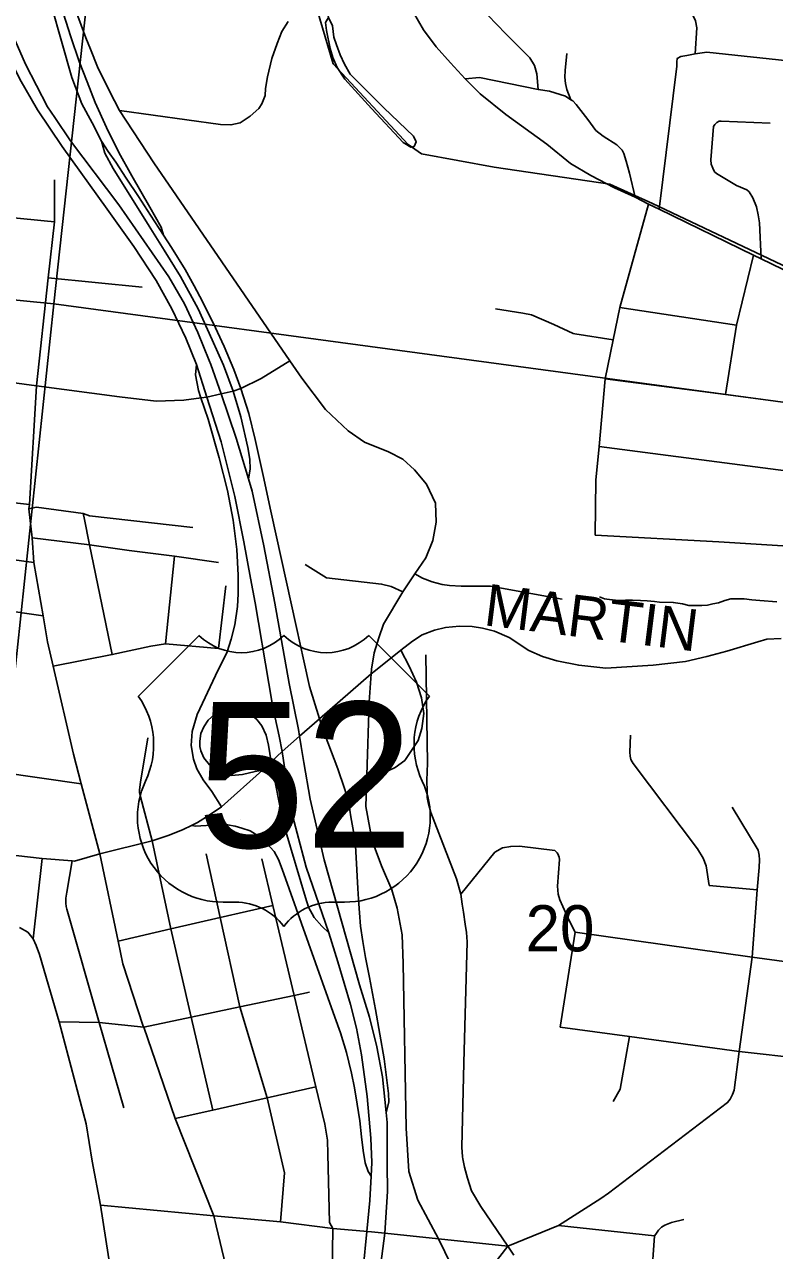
# Model space of a CAD drawing. Extents: x -8.2 to 38.5, y -0.1 to 21.9.
# Drawn here: x 5.706 to 6.385, y 16.265 to 17.376 of the extents above; entities that cross this region are included whole.
import ezdxf

# ---------------------------------------------------------------- set-up
doc = ezdxf.new("R2010")
doc.units = 0
for name, color, linetype in [('GM_X_Adjacent_County_Text', 7, 'Continuous'), ('GM_X_Airport_Location_Class_3', 7, 'Continuous'), ('GM_X_County_Road_Text', 7, 'Continuous'), ('GM_X_Interstate_Location', 7, 'Continuous'), ('GM_X_Major_Lake', 7, 'Continuous'), ('GM_X_Minor_River', 7, 'Continuous'), ('GM_X_State_Location', 7, 'Continuous'), ('GM_X_Township_Road_Text', 7, 'Continuous'), ('GM_X_Township_Subdivision', 7, 'Continuous'), ('GM_X_Township_Subdivision_Text', 7, 'Continuous'), ('GM_X_Township_Text', 7, 'Continuous'), ('GM_X_US_Location', 7, 'Continuous')]:
    doc.layers.add(name, color=color, linetype=linetype)

msp = doc.modelspace()

# ---------------------------------------------------------------- linework, layer by layer
at = {"layer": 'GM_X_Adjacent_County_Text'}
for points in [[(4.7544, 17.3899), (4.8395, 18.1926), (5.838, 18.0925), (5.7325, 17.1233), (5.0356, 17.1922)], [(5.0356, 17.1922), (5.7325, 17.1233), (5.6225, 16.0867), (4.6267, 16.1928), (4.6777, 16.67)]]:
    msp.add_lwpolyline(points, dxfattribs=at)
for points in [[(6.8589, 17.9964), (6.7536, 16.9855), (5.7325, 17.1233), (5.838, 18.0925)], [(5.7325, 17.1233), (6.7536, 16.9855), (6.65, 15.9814), (5.6225, 16.0867)]]:
    msp.add_lwpolyline(points, close=True, dxfattribs=at)
at = {"layer": 'GM_X_Airport_Location_Class_3'}
for p, q in [((5.9523, 16.83), (5.9292, 16.9355)), ((6.0469, 16.8096), (6.0238, 16.791)), ((6.016, 16.6962), (6.0182, 16.7627)), ((5.8844, 16.6676), (5.9215, 16.7008))]:
    msp.add_line(p, q, dxfattribs=at)
for points in [[(5.8671, 17.1255), (5.8595, 17.1397), (5.8513, 17.1545), (5.839, 17.1744), (5.8317, 17.1856), (5.82, 17.2036), (5.8091, 17.2205), (5.7981, 17.2373), (5.7887, 17.2517), (5.7817, 17.2613), (5.7756, 17.2708), (5.7672, 17.2875), (5.7579, 17.3046), (5.7488, 17.3285), (5.7393, 17.3613), (5.7305, 17.3922), (5.7205, 17.4265), (5.7107, 17.455)], [(5.6577, 17.4416), (5.6636, 17.4182), (5.675, 17.3847), (5.6851, 17.361), (5.7015, 17.3269), (5.7176, 17.2991), (5.74, 17.266), (5.7809, 17.2092), (5.8048, 17.1752), (5.8251, 17.1446), (5.8393, 17.1188), (5.8519, 17.0921), (5.8616, 17.0684)], [(5.7655, 17.3541), (5.7613, 17.3643), (5.75, 17.3956)], [(6.0487, 16.8623), (6.0597, 16.8786), (6.0695, 16.8931), (6.0759, 16.9089), (6.079, 16.9255), (6.0782, 16.9426), (6.07, 16.96), (6.0592, 16.973), (6.0486, 16.9825), (6.0356, 16.9891), (6.0139, 16.998), (5.9992, 17.0082), (5.9787, 17.0276), (5.9572, 17.0559), (5.9463, 17.0717), (5.8231, 17.2512), (5.792, 17.2985), (5.7828, 17.3162), (5.772, 17.3382), (5.7655, 17.3541)], [(5.9292, 16.9355), (5.9221, 16.9677), (5.9149, 17.0004), (5.909, 17.0238), (5.9018, 17.0467), (5.8954, 17.0637), (5.8867, 17.0848), (5.8768, 17.1061), (5.8685, 17.1228), (5.8671, 17.1255)], [(5.8616, 17.0684), (5.8609, 17.0589), (5.8634, 17.0449), (5.8657, 17.0381), (5.8723, 17.0188), (5.8821, 16.9838), (5.8897, 16.9541), (5.895, 16.9274), (5.8983, 16.9006), (5.8995, 16.8774)], [(5.8995, 16.8774), (5.8996, 16.8764), (5.8996, 16.8605), (5.8988, 16.849), (5.8965, 16.8324), (5.893, 16.8193), (5.8895, 16.8079), (5.879, 16.7864), (5.8622, 16.7511), (5.8579, 16.7359), (5.8569, 16.723), (5.8589, 16.7107), (5.862, 16.702), (5.8676, 16.6921), (5.8755, 16.6814), (5.8844, 16.6676)], [(6.0182, 16.7627), (6.0202, 16.7923), (6.0226, 16.8072), (6.027, 16.8206), (6.0312, 16.8329), (6.0487, 16.8623)], [(5.9733, 16.7473), (5.9642, 16.7765), (5.9589, 16.7997), (5.9523, 16.83)], [(6.016, 16.6962), (6.0239, 16.6965), (6.0308, 16.6981), (6.0416, 16.703), (6.0505, 16.7096), (6.0564, 16.7185), (6.0627, 16.7277), (6.0659, 16.7386), (6.0676, 16.752), (6.0656, 16.7662), (6.061, 16.7806), (6.0544, 16.7951), (6.0469, 16.8096)], [(6.0238, 16.791), (6.0199, 16.7879), (6.0199, 16.7879), (5.9733, 16.7473)], [(5.9215, 16.7008), (5.9295, 16.7083), (5.9392, 16.7175), (5.955, 16.7314), (5.9733, 16.7473)], [(6.0809, 16.2759), (6.0624, 16.3111), (6.054, 16.3371), (6.0517, 16.3762), (6.0489, 16.5255), (6.0481, 16.5516), (6.0434, 16.5757), (6.0386, 16.5923), (6.0295, 16.614), (6.0208, 16.6366), (6.0153, 16.6677), (6.016, 16.6962)], [(6.0976, 16.2094), (6.0984, 16.2196), (6.097, 16.2346), (6.0925, 16.2524), (6.0809, 16.2759)]]:
    msp.add_lwpolyline(points, dxfattribs=at)
at = {"layer": 'GM_X_Interstate_Location'}
for points in [[(5.8317, 17.1856), (5.8297, 17.1929), (5.8195, 17.2108), (5.8032, 17.2392), (5.7914, 17.2605), (5.78, 17.283), (5.7698, 17.3058), (5.7626, 17.3245), (5.7554, 17.343), (5.7479, 17.3654), (5.7096, 17.4858)], [(5.9089, 16.9647), (5.9104, 16.9735), (5.91, 16.9825), (5.9083, 16.993), (5.9019, 17.0209), (5.8948, 17.0443), (5.8862, 17.0677), (5.8759, 17.0906), (5.8631, 17.1189), (5.8473, 17.1481), (5.8323, 17.172), (5.8188, 17.1938), (5.7863, 17.246), (5.7785, 17.2598), (5.7756, 17.2708)], [(5.9215, 16.7008), (5.915, 16.6995), (5.9033, 16.6968), (5.8933, 16.696), (5.8872, 16.6973), (5.8799, 16.6999), (5.8736, 16.7055), (5.8683, 16.712), (5.8656, 16.7183), (5.8648, 16.7223), (5.8647, 16.727), (5.8657, 16.7339), (5.8685, 16.7399), (5.8722, 16.746), (5.8787, 16.7517), (5.8862, 16.7548), (5.8943, 16.7561), (5.9024, 16.755), (5.9099, 16.7519), (5.9164, 16.7466), (5.9208, 16.741), (5.9247, 16.7324), (5.9271, 16.7235), (5.9295, 16.7083), (5.9369, 16.67), (5.9428, 16.6452), (5.9606, 16.5854), (5.9632, 16.5766), (5.9683, 16.5671), (5.9752, 16.5595), (5.9815, 16.5533)], [(5.9973, 16.6793), (5.9959, 16.6842), (5.9899, 16.7019), (5.9774, 16.7346), (5.9733, 16.7473)], [(6.0335, 16.3906), (6.0361, 16.3999), (6.0358, 16.4076), (6.0319, 16.4392), (6.024, 16.4839), (6.0184, 16.5129), (6.015, 16.5311), (6.0125, 16.5455), (6.0104, 16.5594), (6.0094, 16.5715), (6.0086, 16.5837), (6.008, 16.5936), (6.0063, 16.6216), (6.0057, 16.6321), (6.004, 16.6452), (6.0017, 16.6583), (5.9996, 16.6704), (5.9973, 16.6793)], [(5.8572, 16.6507), (5.8611, 16.6501), (5.8657, 16.6503), (5.8755, 16.6508), (5.8828, 16.6516), (5.8898, 16.6513), (5.8968, 16.65), (5.9027, 16.6483), (5.9104, 16.6456), (5.9185, 16.6405), (5.9252, 16.6347), (5.932, 16.627), (5.936, 16.6198), (5.9393, 16.6109), (5.987, 16.477), (5.9921, 16.4627), (5.9975, 16.445), (5.9998, 16.4362), (6.0021, 16.426), (6.0049, 16.4127), (6.0074, 16.3979), (6.0097, 16.383), (6.0113, 16.3683), (6.0128, 16.3562), (6.0145, 16.345), (6.0173, 16.3371), (6.02, 16.3327)]]:
    msp.add_lwpolyline(points, dxfattribs=at)
at = {"layer": 'GM_X_Minor_River'}
msp.add_lwpolyline([(6.227, 16.8577), (6.2315, 16.856), (6.2425, 16.8546), (6.2505, 16.8547), (6.2569, 16.8549), (6.2641, 16.8544), (6.2702, 16.8542), (6.2767, 16.8536), (6.2812, 16.8531), (6.2938, 16.8528), (6.3021, 16.8514), (6.3078, 16.8501), (6.3131, 16.8499), (6.3196, 16.8501), (6.3249, 16.8504), (6.3295, 16.8514), (6.3348, 16.8524), (6.3406, 16.8545), (6.3459, 16.8559), (6.3528, 16.8561), (6.3581, 16.8559), (6.3649, 16.855), (6.3721, 16.8544), (6.3877, 16.8532)], dxfattribs=at)
at = {"layer": 'GM_X_State_Location'}
msp.add_line((5.9591, 16.7076), (5.9566, 16.7221), dxfattribs=at)
for points in [[(5.8616, 17.0684), (5.8519, 17.0921), (5.8393, 17.1188), (5.8251, 17.1446), (5.8048, 17.1752), (5.7809, 17.2092), (5.74, 17.266), (5.7176, 17.2991), (5.7015, 17.3269), (5.6851, 17.361), (5.675, 17.3847), (5.6636, 17.4182), (5.6577, 17.4416)], [(5.7332, 17.2923), (5.7268, 17.3018), (5.7066, 17.3406), (5.6952, 17.3667), (5.6853, 17.3884), (5.6739, 17.422), (5.6697, 17.4415)], [(5.8732, 17.0719), (5.863, 17.0974), (5.8507, 17.1232), (5.8366, 17.1478), (5.7912, 17.2129), (5.7476, 17.2711), (5.7332, 17.2923)], [(6.0127, 16.2488), (6.0161, 16.2827), (6.0189, 16.3108), (6.02, 16.3327), (6.0206, 16.3452), (6.0198, 16.3673), (6.0165, 16.4051), (6.0112, 16.4426), (6.0066, 16.4669), (6.0013, 16.4883), (5.9898, 16.5271), (5.9815, 16.5533), (5.9612, 16.6129), (5.9501, 16.654), (5.9441, 16.6852), (5.9392, 16.7175), (5.9366, 16.7316), (5.931, 16.7579), (5.9274, 16.7793), (5.9149, 16.8523), (5.9106, 16.8746), (5.9047, 16.9075), (5.8965, 16.9486), (5.884, 16.9983), (5.8712, 17.0388), (5.8616, 17.0684)], [(5.9566, 16.7221), (5.955, 16.7314), (5.954, 16.7375), (5.9458, 16.7793), (5.9326, 16.8521), (5.9228, 16.9039), (5.9122, 16.9535), (5.9089, 16.9647), (5.8978, 17.0015), (5.8842, 17.0417), (5.8746, 17.0684), (5.8732, 17.0719)], [(5.9324, 15.9501), (5.9387, 15.9712), (5.9615, 16.0338), (5.9752, 16.07), (5.9872, 16.1032), (5.9964, 16.1285), (6.0074, 16.1604), (6.0166, 16.1895), (6.0242, 16.2222), (6.0278, 16.2465), (6.0325, 16.281), (6.0349, 16.3189), (6.0345, 16.3435), (6.0344, 16.3815), (6.0335, 16.3906), (6.0303, 16.4228), (6.0252, 16.4499), (6.0186, 16.477), (6.0095, 16.5061), (5.9775, 16.6196), (5.9647, 16.6745), (5.9591, 16.7076)]]:
    msp.add_lwpolyline(points, dxfattribs=at)
at = {"layer": 'GM_X_Township_Subdivision'}
for p, q in [((5.864, 16.8229), (5.809, 16.7679)), ((6.0727, 16.7679), (6.0178, 16.8229)), ((5.8859, 16.5812), (5.8969, 16.5812)), ((5.9848, 16.5812), (5.9958, 16.5812))]:
    msp.add_line(p, q, dxfattribs=at)
for centre, radius, start, end in [((5.9024, 16.8621), 0.0549, 225.573, 314.427), ((5.9793, 16.8621), 0.0549, 225.573, 314.427), ((5.746, 16.7238), 0.0769, 334.5471, 35.0009), ((6.1357, 16.7238), 0.0769, 144.9991, 205.4529), ((5.8851, 16.6581), 0.0769, 154.8319, 270.6383), ((5.9967, 16.6581), 0.0769, 269.3617, 25.1681), ((5.8969, 16.5262), 0.0549, 36.8699, 90), ((5.9848, 16.5262), 0.0549, 90, 143.1301)]:
    msp.add_arc(centre, radius, start, end, dxfattribs=at)
at = {"layer": 'GM_X_Township_Subdivision_Text'}
for p, q in [((5.733, 17.1975), (5.7329, 17.2358)), ((5.7274, 17.1468), (5.8124, 17.1385)), ((6.2452, 17.1201), (6.3511, 17.104)), ((5.5516, 16.9596), (5.7103, 16.9414)), ((5.5482, 16.9124), (5.7144, 16.8888)), ((5.8335, 16.8153), (5.8417, 16.8946)), ((5.9675, 16.8825), (5.9601, 16.8871)), ((5.5464, 16.8657), (5.7228, 16.8406)), ((5.8817, 16.8111), (5.8883, 16.8678)), ((5.6837, 16.6988), (5.7573, 16.6883)), ((6.3264, 16.5962), (6.3699, 16.5923)), ((6.1914, 16.4679), (6.2049, 16.5538)), ((6.2704, 16.1906), (6.2767, 16.2786)), ((6.1437, 16.2695), (6.0976, 16.2094))]:
    msp.add_line(p, q, dxfattribs=at)
for points in [[(6.1712, 17.3176), (6.1701, 17.3317), (6.168, 17.3393), (6.1639, 17.3462), (6.1512, 17.3591), (6.142, 17.3679), (6.1256, 17.3849), (6.1207, 17.3921), (6.1189, 17.3987), (6.1187, 17.408), (6.1221, 17.4326), (6.1244, 17.4395), (6.1304, 17.446), (6.138, 17.4492), (6.144, 17.4506), (6.1869, 17.4425)], [(6.0589, 17.266), (6.0607, 17.2701), (6.0585, 17.2754), (6.0314, 17.3011), (6.0011, 17.3315), (5.9959, 17.3404), (5.9919, 17.3489), (5.9885, 17.3579), (5.9861, 17.365), (5.985, 17.3753), (5.9812, 17.3829), (5.978, 17.4003)], [(6.2879, 17.3926), (6.2964, 17.392), (6.3018, 17.3902), (6.3055, 17.389), (6.3115, 17.3848), (6.3139, 17.3799), (6.3151, 17.3735), (6.3137, 17.3499), (6.3243, 17.3513), (6.4795, 17.3348), (6.49, 17.333)], [(5.792, 17.2985), (5.8836, 17.2858), (5.8929, 17.2855), (5.9013, 17.2875), (5.9103, 17.2933), (5.9181, 17.3003), (5.921, 17.3046), (5.9239, 17.3121), (5.9242, 17.3185), (5.926, 17.329), (5.93, 17.3458), (5.9347, 17.3594), (5.939, 17.3701), (5.9448, 17.3791)], [(6.0589, 17.266), (6.056, 17.2654), (6.0489, 17.2696), (6.0203, 17.3004), (5.9961, 17.327), (5.9892, 17.3375), (5.9854, 17.3465), (5.9827, 17.3547), (5.9796, 17.371), (5.9785, 17.3784), (5.9812, 17.3829)], [(6.2009, 17.3083), (6.1974, 17.3176), (6.196, 17.3229), (6.1954, 17.3287), (6.1958, 17.3348), (6.1974, 17.3503)], [(6.281, 17.2091), (6.2969, 17.3386), (6.2969, 17.3425), (6.2973, 17.3457), (6.3005, 17.3476), (6.3061, 17.3485), (6.3137, 17.3499)], [(6.2593, 17.2201), (6.2542, 17.2418), (6.251, 17.2526), (6.2491, 17.2595), (6.2473, 17.2627), (6.2427, 17.2673), (6.2302, 17.2752), (6.2236, 17.2805), (6.2164, 17.2904), (6.2058, 17.304), (6.2026, 17.3072), (6.2009, 17.3083), (6.1961, 17.3114), (6.1816, 17.316), (6.1712, 17.3176), (6.1182, 17.3284), (6.1052, 17.3272)], [(6.3734, 17.1642), (6.3718, 17.1968), (6.3707, 17.204), (6.3691, 17.2113), (6.3658, 17.2194), (6.3624, 17.2248), (6.3603, 17.2267), (6.3509, 17.2307), (6.3329, 17.2413), (6.3311, 17.243), (6.3296, 17.2463), (6.3282, 17.2498), (6.3278, 17.2539), (6.3303, 17.2839), (6.3313, 17.2859), (6.3331, 17.2876), (6.3353, 17.2888), (6.3373, 17.289), (6.3816, 17.287)], [(6.2231, 16.9138), (6.2237, 16.9636), (6.2265, 16.994), (6.2321, 17.0555), (6.2392, 17.0906), (6.2452, 17.1201), (6.2714, 17.2137)], [(6.3412, 17.0411), (6.3511, 17.104), (6.3666, 17.1675)], [(6.2392, 17.0906), (6.2046, 17.0961), (6.2029, 17.0965), (6.1856, 17.1045), (6.1653, 17.1133), (6.1574, 17.1149), (6.1328, 17.1188)], [(5.5603, 17.0702), (5.7167, 17.049), (5.7918, 17.039), (5.8252, 17.0351), (5.8501, 17.0361), (5.8658, 17.0381), (5.8712, 17.0388), (5.8842, 17.0417), (5.8948, 17.0443), (5.9018, 17.0467), (5.9202, 17.0556), (5.9463, 17.0717)], [(6.2321, 17.0555), (6.3412, 17.0411), (6.4001, 17.0334), (6.5014, 17.0183), (6.5922, 17.0048), (6.6295, 16.9998), (6.6426, 16.9981), (6.7569, 16.9822)], [(6.2265, 16.994), (6.5024, 16.958), (6.6392, 16.9418), (6.7503, 16.9232)], [(5.7097, 16.9376), (5.7166, 16.939), (5.7591, 16.9332)], [(5.7591, 16.9332), (5.7647, 16.9311), (5.8583, 16.9207)], [(5.7854, 16.8055), (5.7647, 16.9048), (5.7599, 16.9294), (5.7591, 16.9332)], [(6.2231, 16.9138), (6.3351, 16.9077), (6.393, 16.904), (6.4956, 16.8935)], [(6.0487, 16.8623), (6.0382, 16.8673), (6.0294, 16.8693), (5.9794, 16.8751), (5.9675, 16.8825)], [(6.0597, 16.8786), (6.0666, 16.8747), (6.0754, 16.8714), (6.0842, 16.8689), (6.0911, 16.868), (6.1015, 16.8675), (6.1282, 16.8674), (6.193, 16.8557)], [(5.7319, 16.795), (5.7854, 16.8055), (5.8204, 16.8132), (5.8335, 16.8153), (5.8817, 16.8111)], [(6.3264, 16.5962), (6.3237, 16.6141), (6.3208, 16.621), (6.3157, 16.6295), (6.2574, 16.7068), (6.2564, 16.7083), (6.2553, 16.7105), (6.2546, 16.7135), (6.2544, 16.7169), (6.2551, 16.7324)], [(5.8764, 16.3927), (5.857, 16.4768), (5.8385, 16.5569), (5.8216, 16.6367), (5.8111, 16.6765), (5.8102, 16.6805), (5.81, 16.6827), (5.811, 16.6902), (5.8128, 16.7008), (5.8176, 16.7299)], [(6.3653, 16.5312), (6.3699, 16.5923), (6.3715, 16.6125), (6.372, 16.6196), (6.3717, 16.6238), (6.3707, 16.6283), (6.3472, 16.6672)], [(6.1013, 16.5884), (6.132, 16.6263), (6.1389, 16.6303), (6.1465, 16.6317), (6.1545, 16.6319), (6.1863, 16.6279), (6.1884, 16.6259), (6.1892, 16.6248), (6.1903, 16.622), (6.1907, 16.6198), (6.1887, 16.5955), (6.1893, 16.5883), (6.191, 16.5831), (6.199, 16.565), (6.2049, 16.5538), (6.3653, 16.5312)], [(5.9379, 16.2913), (5.9414, 16.3359), (5.9258, 16.4038), (5.9009, 16.4861), (5.8832, 16.5672), (5.8706, 16.625)], [(5.7958, 16.3947), (5.7736, 16.4721), (5.7442, 16.5747), (5.7437, 16.5772), (5.7433, 16.5801), (5.7434, 16.5847), (5.7442, 16.5903), (5.7491, 16.6186)], [(5.9847, 16.2434), (5.9853, 16.2854), (5.9821, 16.2908), (5.9807, 16.3528), (5.9803, 16.3654), (5.9779, 16.3799), (5.9699, 16.4137), (5.9503, 16.4965), (5.9309, 16.5782), (5.9209, 16.6204)], [(5.7906, 16.5459), (5.8385, 16.5569), (5.8832, 16.5672), (5.9309, 16.5782)], [(5.7372, 16.4728), (5.7736, 16.4721), (5.8139, 16.4677), (5.857, 16.4768), (5.9009, 16.4861), (5.9503, 16.4965), (5.964, 16.4994)], [(6.1914, 16.4679), (6.2542, 16.4593), (6.3536, 16.4457), (6.4131, 16.4391), (6.4721, 16.4364), (6.5007, 16.4351), (6.5454, 16.4341), (6.608, 16.4328), (6.6976, 16.4257)], [(6.2394, 16.4005), (6.2457, 16.4117), (6.2474, 16.422), (6.2542, 16.4593)], [(5.8423, 16.385), (5.8764, 16.3927), (5.9258, 16.4038), (5.9699, 16.4137)], [(5.7746, 16.3066), (5.8774, 16.2968), (5.9379, 16.2913), (5.9853, 16.2854), (6.0203, 16.2822), (6.0325, 16.281), (6.0809, 16.2759)], [(6.1898, 16.288), (6.2767, 16.2786), (6.2779, 16.2803), (6.2803, 16.2838), (6.2831, 16.2867), (6.286, 16.2883), (6.2922, 16.2908), (6.3032, 16.2936)]]:
    msp.add_lwpolyline(points, dxfattribs=at)
at = {"layer": 'GM_X_Township_Text'}
for p, q in [((5.722, 16.6208), (5.7137, 16.5478)), ((6.0809, 16.2759), (6.1437, 16.2695))]:
    msp.add_line(p, q, dxfattribs=at)
for points in [[(6.051, 17.3982), (6.0585, 17.3872), (6.0675, 17.3716), (6.079, 17.3562), (6.0919, 17.3417), (6.1052, 17.3272), (6.1188, 17.3136), (6.142, 17.2948), (6.1793, 17.2681), (6.2005, 17.2506), (6.2191, 17.2397), (6.2405, 17.2285), (6.2593, 17.2201), (6.2714, 17.2137), (6.281, 17.2091), (6.3666, 17.1675), (6.3734, 17.1642), (6.3926, 17.1547), (6.4039, 17.1479), (6.4172, 17.1386), (6.4443, 17.1187), (6.4501, 17.1156), (6.4585, 17.1123)], [(5.733, 17.1975), (5.7237, 17.1984), (5.5738, 17.2134)], [(5.8796, 16.2877), (5.8774, 16.2968), (5.8423, 16.385), (5.8139, 16.4677), (5.8135, 16.4686), (5.7949, 16.5252), (5.7906, 16.5459), (5.774, 16.6248), (5.7573, 16.6883), (5.7502, 16.7152), (5.7319, 16.795), (5.7268, 16.8171), (5.7228, 16.8406), (5.7144, 16.8888), (5.7129, 16.9114), (5.7097, 16.9376), (5.7103, 16.9414), (5.7167, 17.049), (5.7274, 17.1468), (5.733, 17.1975)], [(5.7129, 16.9114), (5.7647, 16.9048), (5.8008, 16.8998), (5.8417, 16.8946), (5.8816, 16.8888)], [(6.0469, 16.8096), (6.0573, 16.8176), (6.0662, 16.8234), (6.0775, 16.8277), (6.0874, 16.8299), (6.0999, 16.8313), (6.1116, 16.8309), (6.1209, 16.8293), (6.1318, 16.8266), (6.1451, 16.8209), (6.1629, 16.8092), (6.1753, 16.8036), (6.1882, 16.7999), (6.2081, 16.7958), (6.2327, 16.7931), (6.2755, 16.7959), (6.3047, 16.7991), (6.3242, 16.8036), (6.3424, 16.8087), (6.3703, 16.8171), (6.3784, 16.8193), (6.3914, 16.8201)], [(6.0695, 16.8051), (6.0699, 16.7857), (6.0709, 16.707), (6.0704, 16.6913), (6.0706, 16.6818), (6.0707, 16.6759), (6.0716, 16.6714), (6.074, 16.6624), (6.0972, 16.6022), (6.1013, 16.5884), (6.1026, 16.5792), (6.1036, 16.5721), (6.1051, 16.5613), (6.1064, 16.5537), (6.1069, 16.5453), (6.1041, 16.4355), (6.1021, 16.3592), (6.1028, 16.3502), (6.1032, 16.3484)], [(5.5949, 16.6344), (5.5955, 16.634), (5.6739, 16.6262), (5.722, 16.6208), (5.7491, 16.6186), (5.7513, 16.6184), (5.774, 16.6248), (5.8216, 16.6367), (5.837, 16.6419), (5.8496, 16.647), (5.8572, 16.6507), (5.8625, 16.6533), (5.8733, 16.6598), (5.8844, 16.6676)], [(5.7014, 16.5581), (5.709, 16.5539), (5.7137, 16.5478), (5.7165, 16.5417), (5.7193, 16.5338), (5.7372, 16.4728), (5.7616, 16.3802), (5.7673, 16.3464), (5.7746, 16.3066), (5.794, 16.1822)], [(6.1437, 16.2695), (6.1898, 16.288), (6.2281, 16.3126), (6.235, 16.3174), (6.3429, 16.3995), (6.3452, 16.4025), (6.3474, 16.4068), (6.3488, 16.4108), (6.3536, 16.4457), (6.3653, 16.5312)], [(6.3653, 16.5312), (6.4324, 16.5223), (6.4668, 16.5177), (6.646, 16.4936), (6.6528, 16.4942), (6.6648, 16.5007)], [(6.1032, 16.3484), (6.1046, 16.3411), (6.1074, 16.331), (6.111, 16.3196), (6.1194, 16.3053), (6.1437, 16.2695), (6.1492, 16.2612)], [(5.9129, 16.053), (5.9296, 16.0514), (5.9066, 16.1716), (5.8883, 16.2513), (5.8796, 16.2877)]]:
    msp.add_lwpolyline(points, dxfattribs=at)
at = {"layer": 'GM_X_US_Location'}
msp.add_lwpolyline([(5.9662, 17.4064), (5.9857, 17.3408), (6.0536, 17.2676), (6.0656, 17.2593), (6.1316, 17.2472), (6.2364, 17.2318), (6.2749, 17.2142), (6.398, 17.1559), (6.4557, 17.1126), (6.7633, 17.0468), (6.8914, 16.9695), (6.9592, 16.9572), (6.9787, 16.9469), (7.0844, 16.832), (7.1474, 16.6761), (7.2926, 16.4169)], dxfattribs=at)

# ---------------------------------------------------------------- texts
at = {"layer": 'GM_X_County_Road_Text'}
msp.add_text('20', height=0.04186, rotation=0, dxfattribs=at).set_placement((6.16, 16.5365))
at = {"layer": 'GM_X_Major_Lake'}
msp.add_text('MARTIN', height=0.03788, rotation=352.9064, dxfattribs=at).set_placement((6.1211, 16.8322))
at = {"layer": 'GM_X_Township_Road_Text'}
for s in ['0', '/']:
    msp.add_text(s, height=0.000189, dxfattribs=at).set_placement((5.9408, 16.6955))
msp.add_text('52', height=0.000189, rotation=0, dxfattribs=at).set_placement((5.9017, 16.6563))
at = {"layer": 'GM_X_Township_Subdivision'}
msp.add_text('52', height=0.13184, dxfattribs=at).set_placement((5.8621, 16.6306))

doc.saveas('drawing.dxf')
